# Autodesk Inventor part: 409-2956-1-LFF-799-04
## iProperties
Created: 2010-11
Part Number: 409-2956-1-LFF-799-04
Material: 3/4" OD TUBE - SS
Document SubType Name: Modeling
Designer: S. Boerckel
Engineer: Steve Boerckel
Mass: 731.966 g
Surface Area: 1099.2 cm^2
Volume: 90.5898 cm^3
Density: 8.08 g/cm^3
Description: DRAIN TUBING
Length: 39.254 in
Author: S. Boerckel
Revision Number: 0
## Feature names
1. Sweep2
